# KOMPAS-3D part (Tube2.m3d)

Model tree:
1. Plane XY
2. Plane ZX
3. Plane ZY
4. X Axis
5. Y Axis
6. Z Axis
7. Origin
8. Sketch:1
9. Extrude:1
     Wall Thickness 1 = 1; Wall Thickness 2 = 8; Distance 1 = 2490; Distance 2 = 10

Referenced files in D:\Documents and Settings\kashirsky\Рабочий стол\Seminar\: Cottage_balcony.a3d
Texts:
  Steel DIN 17102
  Three Point Plane
  Plane at Angle
  Line and Point Plane
  Axis through Two Vertices
  Axis of Feature
  Axis of Conical Surface
  Axis through Edge
  Trim by Surface
  Trim by Sketch
  Feature with No History
  Intersection Axis of Two Planes
  Two Line Plane
  Line and Face Plane
  Bend by line
  Hole in sheet body
  Cut in sheet body
  Point in CM
  Linear Dimension from Line to Point
  Surface Finish Symbol
  Geometric Tolerance Symbol
  Leader #1
  Leader #2
  Leader #3
  Shape Deviations and Datum
  Node point number
  Mark of coordination axis
  Node point designation
  Mark/Reference designation with leader
  Mark/reference designation on line
  Mark/Reference designation without leader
